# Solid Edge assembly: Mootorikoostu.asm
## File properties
Author: Türk
Template: Iso Assembly.asm
Last saved by: kalle
Revision: 47
Application: Solid Edge
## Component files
kolvikoostu.asm
SILINDER.par
MootorSilindripea.asm
lipann.par
ll.par
nal.par
Keps.par
llihammasratas.par
igukastikoostu.asm
llisaale.par
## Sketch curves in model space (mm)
circle centre (240, 245, 0) radius 5.7295
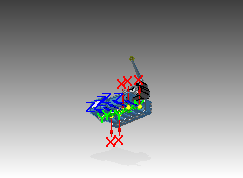
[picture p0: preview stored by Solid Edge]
